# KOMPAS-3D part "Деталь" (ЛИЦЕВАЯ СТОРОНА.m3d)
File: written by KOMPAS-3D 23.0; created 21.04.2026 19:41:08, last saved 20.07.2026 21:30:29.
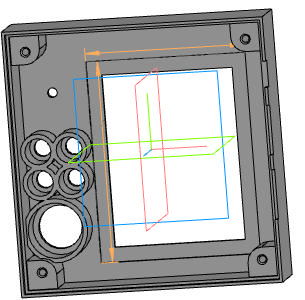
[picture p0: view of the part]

Document properties: Автор: D.LAB; Полное имя файла: C:\ЭЛЕКТРОНИКА\СХЕМЫ\Разное\ЦИФРОВОЙ ПРЕССОСТАТ ДЛЯ КОМПРЕССОРА\2.0 (питание от внешнего 12В)\Корпус\ЛИЦЕВАЯ СТОРОНА.m3d

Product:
- Part/product: Деталь
    Масса: 0.243689

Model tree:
1. ОСНОВАНИЕ
2. Элемент выдавливания:1
     Расстояние 1 = 22
3. Эскиз:2  (with: Элемент выдавливания:1)
4. Элемент выдавливания:2
     Расстояние 2 = 2.5
5. Эскиз:3  (with: Элемент выдавливания:2, Элемент выдавливания:1)
6. Элемент выдавливания:3
     Расстояние 2 = 1.5
7. Эскиз:4  (with: Элемент выдавливания:3)
8. Элемент выдавливания:4
     Расстояние 2 = 15
9. Фаска:1  (with: Элемент выдавливания:4)
     Угол = 60; Длина 1 = 0.5; Длина 2 = 0.866025
10. Эскиз:5  (with: Элемент выдавливания:3)
11. Элемент выдавливания:5
     Расстояние 2 = 16
12. ВЫРЕЗЫ НА ЛИЦЕВОЙ СТОРОНЕ  (with: Элемент выдавливания:5, Элемент выдавливания:3)
13. Элемент выдавливания:6
     Расстояние 1 = 20; Расстояние 2 = 2
14. Эскиз:7  (with: Элемент выдавливания:5, Элемент выдавливания:6)
15. Элемент выдавливания:7
     Расстояние 2 = 1
16. Эскиз:8  (with: Элемент выдавливания:5, Элемент выдавливания:6)
17. Элемент выдавливания:8
     Расстояние 1 = 11
18. Элемент выдавливания:9  (with: Элемент выдавливания:8)
     Расстояние 2 = 20
19. Эскиз:9  (with: Элемент выдавливания:8, Элемент выдавливания:9)
20. Элемент выдавливания:11
     Расстояние 2 = 11
21. ВЫРЕЗЫ ПОД ПРОВОДА  (with: Элемент выдавливания:1, Элемент выдавливания:2, Элемент выдавливания:3)
22. Элемент выдавливания:12
     Расстояние 2 = 1.5
23. ВЫРЕЗ ПОД ПИТАНИЕ  (with: Элемент выдавливания:1, Элемент выдавливания:2, Элемент выдавливания:3)
24. Элемент выдавливания:14  (with: Элемент выдавливания:2)
     Расстояние 2 = 2.5
25. НАДПИСЬ  (with: Элемент выдавливания:1)
26. Элемент выдавливания:15
     Расстояние 2 = 0.5
27. Эскиз:12  (with: Элемент выдавливания:1, Элемент выдавливания:15)
28. Элемент выдавливания:16
     Расстояние 2 = 1
29. Линейный размер:1  (with: Элемент выдавливания:5, Элемент выдавливания:7)
     Значение = 55
30. Линейный размер:3  (with: Элемент выдавливания:5, Элемент выдавливания:7)
     Значение = 69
